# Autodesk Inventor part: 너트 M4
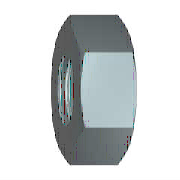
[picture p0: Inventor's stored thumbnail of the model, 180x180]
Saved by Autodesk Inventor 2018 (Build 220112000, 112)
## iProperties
Created: 2012-02
Part Number: 너트 M4
Material: 강철, 연강
Description: 6각 너트 및 6각 가는 너트 - 스타일 1
Document SubType Name: Modeling
Standard: KS B 1012
Designer: mduedu
Standards Organization: KS
Language: ko-KR
Size Designation: A M4
Categories: <MemberInstance><Categories><Category DisplayName="조임쇠" InternalName="e4da775c-781d-43d5-af7c-5136215cf5a6" Mnemonic="FSTN"><Category DisplayName="너트" InternalN
Density: 7.85 g/cm^3
Appearance: 강철
Mass: 0.84562 g
Surface Area: 1.71448 cm^2
Volume: 0.107722 cm^3
IsCustomPart: 0
Author: mduedu
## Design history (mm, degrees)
sketch "스케치1"
  geometry: L1 (-4.041, 0)-(-2.021, 3.5); L2 (-2.021, 3.5)-(2.021, 3.5); L3 (2.021, 3.5)-(4.041, 0); L4 (4.041, 0)-(2.021, -3.5); L5 (2.021, -3.5)-(-2.021, -3.5); L6 (-2.021, -3.5)-(-4.041, 0); 2 further points
  constraints: 12 end point, 1 coincident, 1 horizontal, 11 other
  dimensions: "d0" = 8.0829 distance of L3.end L1.start (= 1.1547 x SW)
extrude "본체" new body sketch "스케치1" distance "d1" = 3.2 (= KOH); taper "d2" = 0 deg
sketch "스케치2"
  geometry: L1 (0, 2.021)-(0, 4.041) reference; L2 (0, 4.041)-(3.2, 4.041) reference; L3 (3.2, 2.021)-(3.2, 4.041) reference; L4 (-0.64, 0)-(3.84, 0) reference; L5 (0.313, 4.041)-(0, 3.5); L6 (2.887, 4.041)-(3.2, 3.5)
  constraints: 4 end point, 4 point on line
  dimensions: "d3" = 30 deg angle of L1 L5 (= ANG1); "d4" = 30 deg angle of L3 L6 (= ANG2); "d5" = 7 diameter of L5.end L4 (= SW0); "d6" = 7 diameter of L6.end L4 (= SW01)
revolve "모따기1" sketch "스케치2" stored, may be unused: angle "d7" = 90 deg
sketch "스케치3"
  geometry: A1 r 3.5 centre (0, 0) between (-1.75, -3.031) and (1.75, -3.031) reference; 1 further point
  constraints: 1 coincident
hole "스레드" sketch "스케치3" at (0, 0) diameter "d25" = 3.242; stored, may be unused: countersink angle "d29" = 82 deg, drill point angle "d31" = 118 deg; dims "d26" = 6, "d27" = 4, "d28" = 2, "d30" = 8
workaxis "Work Axis1"
workplane "Work Plane1"
body "Solid1"
chamfer "모따기2" distance "d8" = 0.37889 (= -0.5 x GD1 + 0.5 x NND); stored, may be unused: angle "d9" = 30 deg, second distance "d40" = 0.37889 (= -0.5 x GD1 + 0.5 x NND)
chamfer "모따기3" distance "d10" = 0.37889 (= -0.5 x GD1 + 0.5 x NND); stored, may be unused: angle "d11" = 30 deg, second distance "d41" = 0.37889 (= -0.5 x GD1 + 0.5 x NND)
other parameters: "ANG1" = 30 deg [user parameter; used in 1 equation term], "ANG2" = 30 deg [user parameter; used in 1 equation term], "NND" = 4 [user parameter; used in 4 equation terms], "KOH" = 3.2 [user parameter; used in 1 equation term], "SW" = 7 [user parameter; used in 4 equation terms], "SW0" = 7 (= SW) [user parameter; used in 1 equation term], "SW01" = 7 (= SW) [user parameter; used in 1 equation term], "GD1" = 3.24223 (computed from THREADDIA, PTC, TOA) [user parameter; used in 4 equation terms], "d13" = 0, "d14" = 0, "d39" = 0, "d42" = 0, "GUL" = 0.37889 (= 0.541266 x PTC) [user parameter], "TPU" = 14.28571 (computed from PTC) [user parameter], "THREADDIA" = 4 [user parameter; used in 1 equation term], "TOA" = 30 deg [user parameter; used in 1 equation term], "PTC" = 0.7 [user parameter; used in 4 equation terms], "E0" = 8.085 (= 1.155 x SW) [user parameter], "GAL" = 0.37889 (= 0.541266 x PTC) [user parameter]
